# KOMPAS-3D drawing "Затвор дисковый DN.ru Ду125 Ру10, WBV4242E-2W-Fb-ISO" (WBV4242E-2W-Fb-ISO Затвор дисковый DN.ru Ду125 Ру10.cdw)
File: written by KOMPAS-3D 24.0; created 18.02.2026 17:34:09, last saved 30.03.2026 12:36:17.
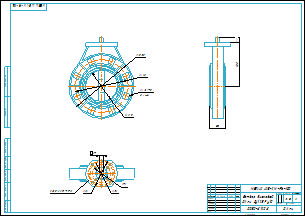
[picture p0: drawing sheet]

Document properties: Автор: R2D2; Форматы листов документа: A2; Полное имя файла: WBV4242E-2W-Fb-ISO Затвор дисковый DN.ru Ду125 Ру10.m3d; Масса: 3.26; Наименование: Затвор дисковый DN.ru Ду125 Ру10; Количество листов документа: 1; Примечание: D050-81208

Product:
- Part/product: Затвор дисковый DN.ru Ду125 Ру10  | designation WBV4242E-2W-Fb-ISO
    Масса: 3.26
    Раздел спецификации: Прочие изделия
    Примечание: D050-81208

Views: Вид 1, Спереди, Проекционный вид 2, Проекционный вид 3
Referenced files in E:\Работа\Зайцев\WBV4242E-2W-Fb-ISO Затвор дисковый DN.ru Ду50-200 Ру10\DN125\: WBV4242E-2W-Fb-ISO Затвор дисковый DN.ru Ду125 Ру10.m3d
Referenced files in E:\Работа\Зайцев\Для компаса\: чертеж DN.ru А3.cdt
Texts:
  WBV4242E-2W-Fb-ISO
  ISO 5211 F07/F10
  чертеж DN.ru А3.cdt
  Затвор дисковый
  DN.ru Ду125 Ру10
  Затвор дисковый DN.ru Ду125 Ру10
  WBV4242E-2W-Fb-ISO Затвор дисковый DN.ru Ду125 Ру10
Dimensions and other numbers on the sheet: 0; 3; 2; 4; 253,5; 208; 125; 8 отв.; 22; 169; 63; 6; 5; 102; 90; 70; 17; 1:2; 1; 3,26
